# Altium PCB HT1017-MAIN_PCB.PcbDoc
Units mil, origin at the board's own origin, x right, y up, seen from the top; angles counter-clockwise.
Board outline 625 x 820 mil, 2 copper layers (Top Layer, Bottom Layer); 15 components, 37 nets, 57 pads, 70 vias.
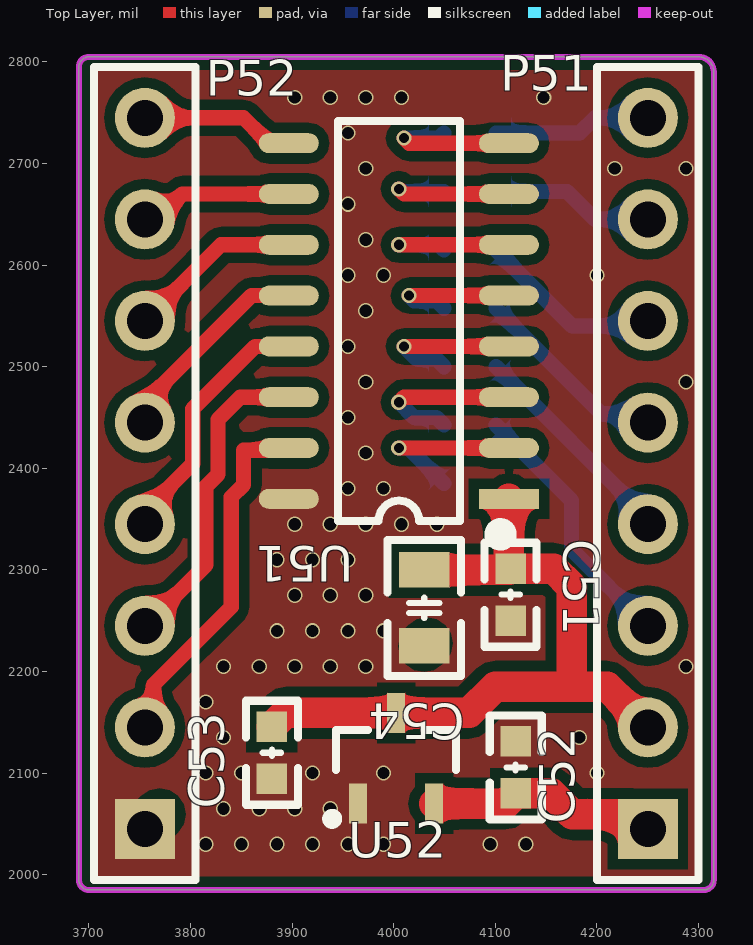
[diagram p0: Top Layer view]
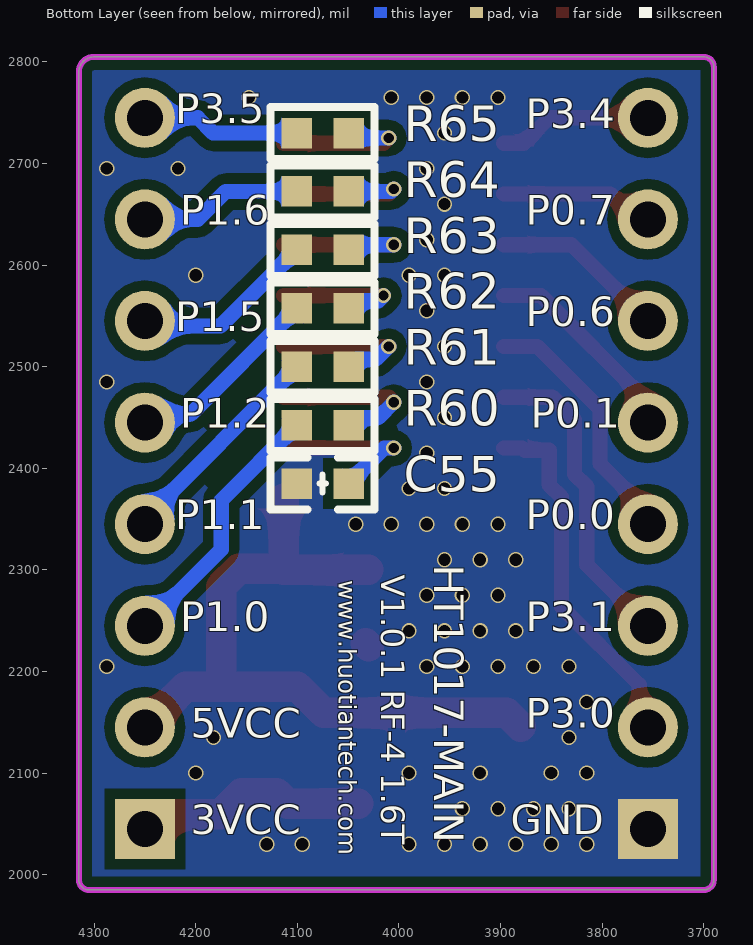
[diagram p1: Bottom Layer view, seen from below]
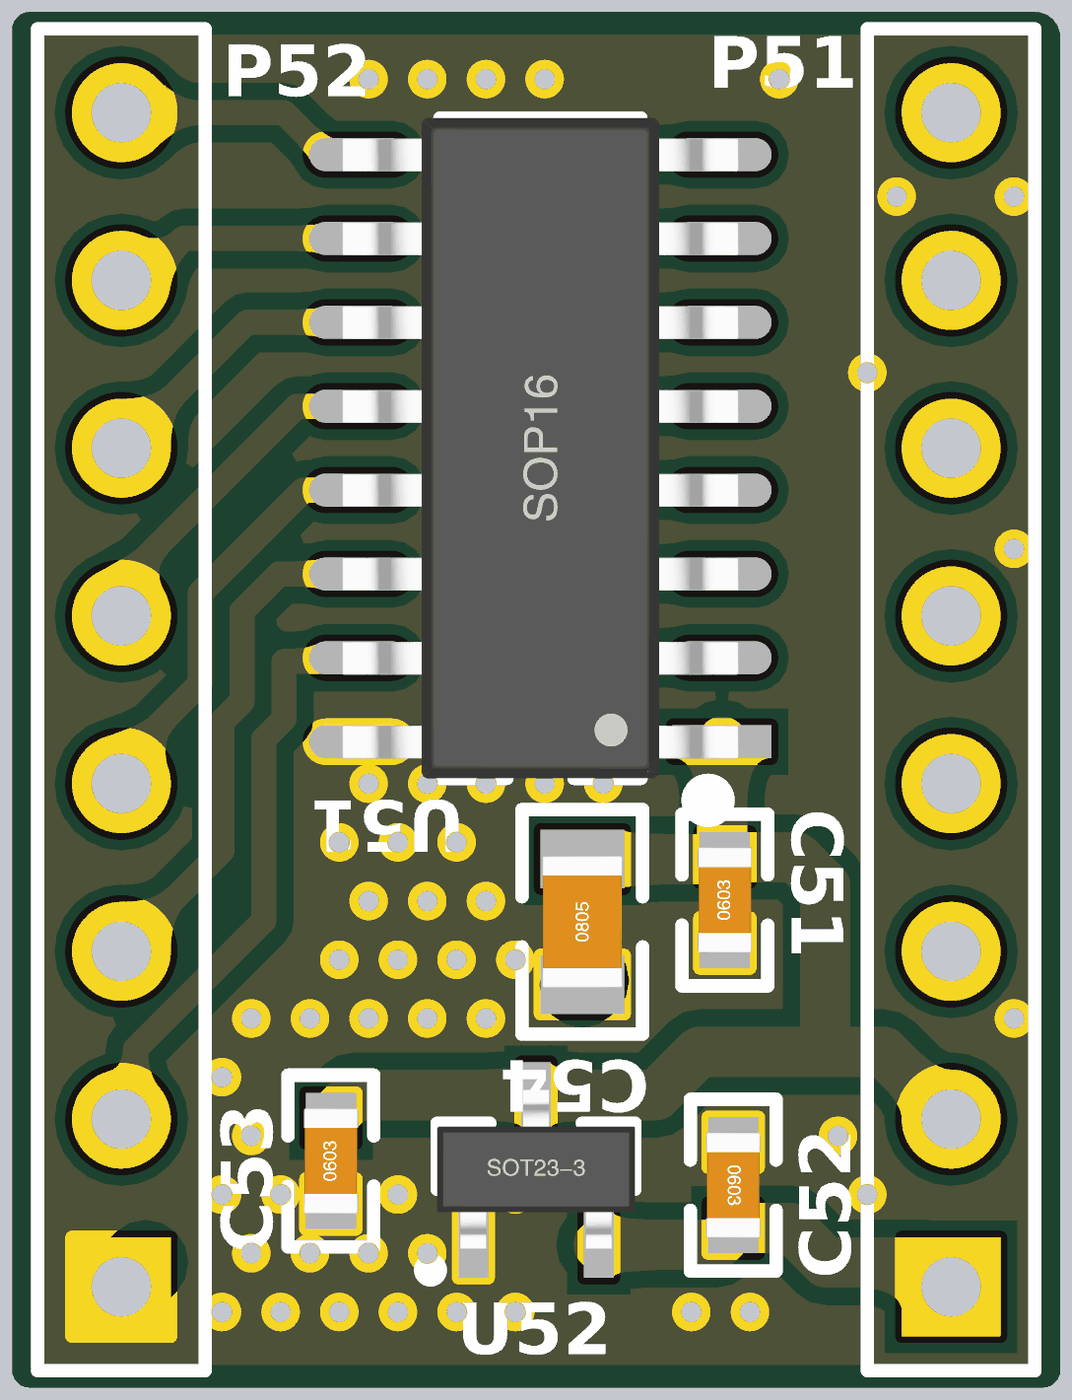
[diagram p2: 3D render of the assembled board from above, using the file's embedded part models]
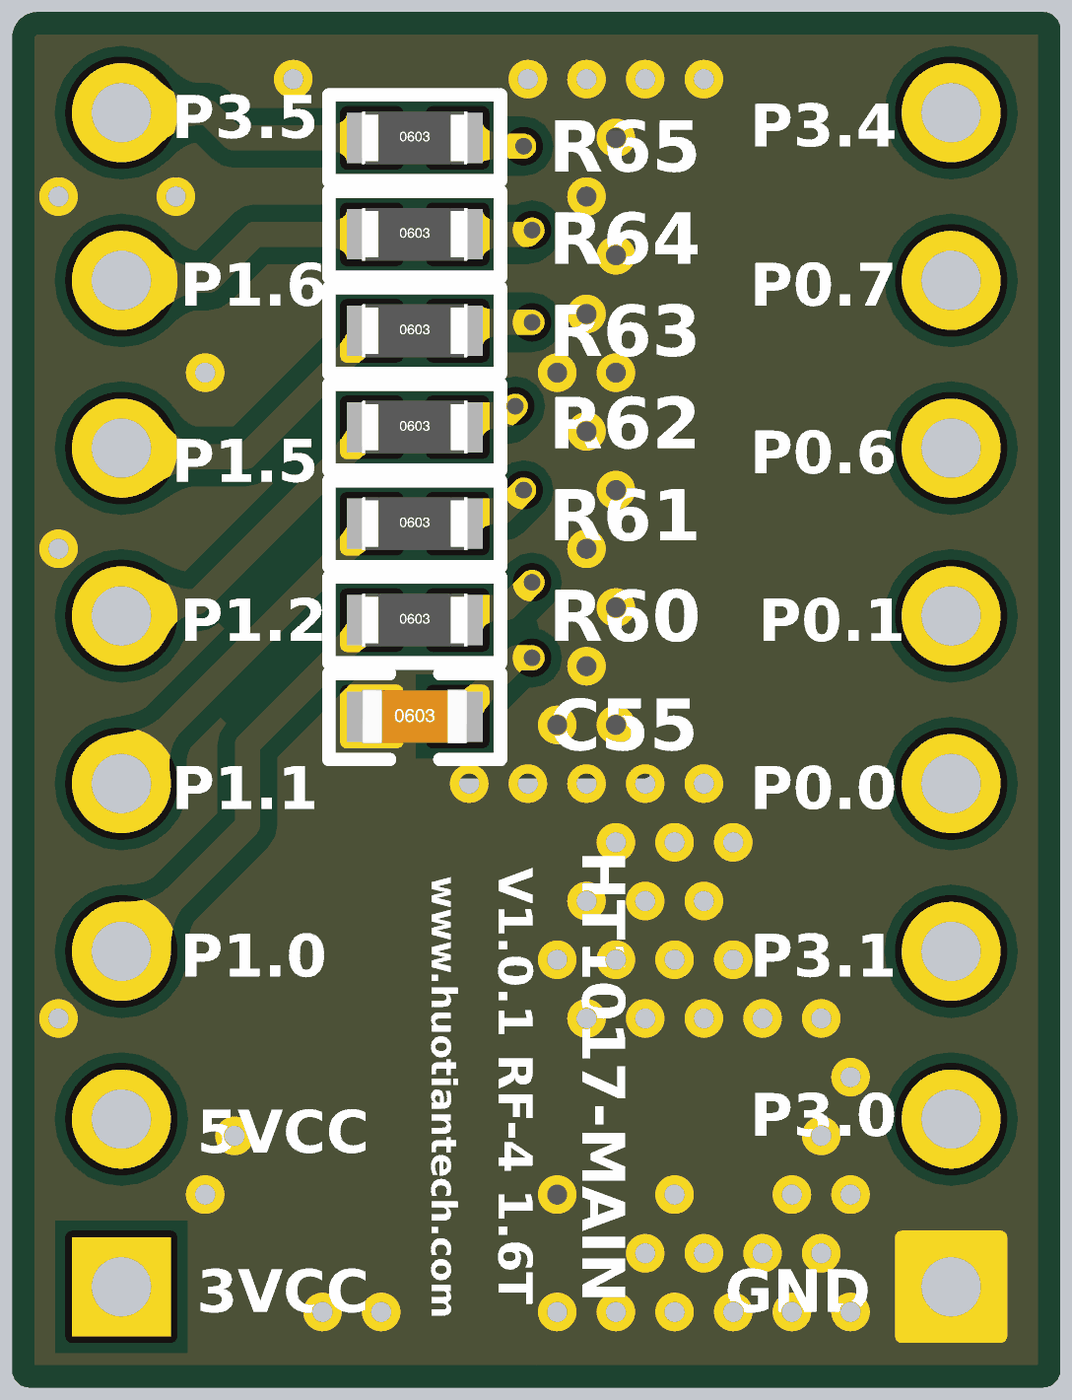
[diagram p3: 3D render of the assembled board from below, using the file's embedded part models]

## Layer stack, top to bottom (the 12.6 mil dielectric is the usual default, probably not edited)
Top Solder: solder mask 0.4, Solder Resist, Dk 3.5
Top Layer: signal copper 1.4
Dielectric 1: dielectric 12.6, FR-4, Dk 4.8
Bottom Layer: signal copper 1.4
Bottom Solder: solder mask 0.4, Solder Resist, Dk 3.5

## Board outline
3690,1995 ccw(c3700,1995) 3700,1985 4305,1985 ccw(c4305,1995) 4315,1995 4315,2790 ccw(c4300,2790) 4300,2805 3700,2805 ccw(c3700,2795) 3690,2795

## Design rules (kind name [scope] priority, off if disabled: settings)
Clearance [All] p1: gap=10 ignorepadtopadclearanceinfootprint=FALSE except(0: Arc-Hole Track-Hole SMDPad-Hole THPad-Hole Via-Hole Fill-Hole Poly-Hole Region-Hole Text-Hole)
HoleSize [All] p1: absolutevalues=TRUE maxlimit=100 minlimit=10 maxpercent=80.000 minpercent=20.000
PlaneConnect [All] p1: planeconnectstyle=Direct reliefexpansion=20 reliefentries=4 reliefconductorwidth=10 reliefairgap=10
PolygonConnect [All] p1: connectstyle=Direct reliefconductorwidth=10 reliefentries=4 polygonreliefangle="90 Angle" airgapwidth=10
RoutingVias [All] p1: holewidth=15 width=30 viastyle="Through Hole" minholewidth=10 minwidth=15 maxholewidth=30 maxwidth=50
SolderMaskExpansion [All] p1: expansion=4
Width [All] p1: maxlimit=50 minlimit=10 preferedwidth=30
28 further rules are at their usual default settings.

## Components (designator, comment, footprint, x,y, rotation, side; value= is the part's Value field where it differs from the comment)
C51 "Cap" "C 0603_L" 4115,2275.59 r90 top value=1uF
C52 "Cap" "C 0603_L" 4120,2105.59 r270 top value=1uF
C53 "Cap" "C 0603_L" 3880,2120 r90 top value=104
C54 "Cap" "C 0805_L" 4030,2262.6 r90 top value=10uF
C55 "Cap" "C 0603_L" 4075,2385 r180 bottom value=223±5%
P51 "Header 8" HDR1X8 4250,2045 r90 top
P52 "Header 8" HDR1X8 3755,2045 r90 top
R60 "Res1" "R 0603_L" 4075,2442.5 r180 bottom value=3.3K
R61 "Res1" "R 0603_L" 4075,2500 r180 bottom value=3.3K
R62 "Res1" "R 0603_L" 4075,2557.5 r180 bottom value=3.3K
R63 "Res1" "R 0603_L" 4075,2615 r180 bottom value=3.3K
R64 "Res1" "R 0603_L" 4075,2672.5 r180 bottom value=3.3K
R65 "Res1" "R 0603_L" 4075,2730 r180 bottom value=3.3K
U51 "CA51F351S3" SOP16_L 4005,2545 r180 top
U52 "XC6206P302MR" SOT23-3L 4002.4,2115 r0 top

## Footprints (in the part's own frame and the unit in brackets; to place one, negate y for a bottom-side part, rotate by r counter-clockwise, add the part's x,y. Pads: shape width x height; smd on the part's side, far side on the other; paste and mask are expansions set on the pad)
"C 0603_L" [mil] "无极性贴片电容"
  rect 30x30 smd: 1(-25.59,0) 2(25.59,0)
  silkscreen extent -51,-26 51,26, body extent -31,-16 31,16, height 32
"C 0805_L" [mil] "无极性贴片电容                    @sucaita.com 素材塔"
  rect 35x50 smd: 1(-37.4,0) 2(37.4,0)
  silkscreen extent -67,-36 67,36, body extent -39,-24 39,24, height 20
HDR1X8 [mm] "Connector; Header; 8 Position"
  rect 1.5x1.5 hole 0.9: 1(0,0)
  round 1.5 hole 0.9: 2(2.54,0) 3(5.08,0) 4(7.62,0) 5(10.16,0) 6(12.7,0) 7(15.24,0) 8(17.78,0)
  silkscreen extent -1.27,-1.27 19.05,1.27
"R 0603_L" [mil] "1/10W贴片电阻"
  rect 30x30 smd: 1(-25.59,0) 2(25.59,0)
  silkscreen extent -51,-26 51,26, body extent -31,-16 31,16, height 16
SOP16_L [mm] "10.3*6.2*1.8mm（长宽高）"
  rect 1.5x0.5 smd: 1(-2.752,4.445)
  oval 1.5x0.5 smd: 2(-2.752,3.175) 3(-2.752,1.905) 4(-2.752,0.635) 5(-2.752,-0.635) 6(-2.752,-1.905) 7(-2.752,-3.175) 8(-2.752,-4.445) 9(2.752,-4.445) 10(2.752,-3.175) 11(2.752,-1.905) 12(2.752,-0.635) 13(2.752,0.635) 14(2.752,1.905) 15(2.752,3.175) 16(2.752,4.445)
  silkscreen extent -2.69,-5 1.52,5.49, body extent -3,-5 3,5, height 1.9
SOT23-3L [mm] "3x1.3x1mm(长宽高)"
  rect 0.45x1 smd: 1(-0.95,-1.143) 2(0.95,-1.143) 3(0,1.125)
  silkscreen extent -1.72,-1.65 1.5,0.7, body extent -1.5,-1.2 1.5,1.2, height 1.05

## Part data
C51 C52 C53 C54 C55: "电容"
P51 P52: "Header, 8-Pin"
R60 R61 R62 R63 R64 R65: "电阻"
U52: "稳压IC"

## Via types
v1: diameter 15, hole 12, Top Layer to Bottom Layer, 63 vias
v2: diameter 15, hole 10, Top Layer to Bottom Layer, 7 vias

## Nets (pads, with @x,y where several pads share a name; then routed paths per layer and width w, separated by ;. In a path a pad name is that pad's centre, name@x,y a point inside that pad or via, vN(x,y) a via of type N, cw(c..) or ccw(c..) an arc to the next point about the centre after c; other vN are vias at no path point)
3.0V/VCC: C52.2 P51.1 U52.2 | length 228.8
  Top Layer w30: U52.2 4110,2070 C52.2 4155,2080 4175.47,2059.53 4235.47,2059.53 P51.1
5V/0.2A: 
5V/VCC: C51.2 C53.2 C54.2 P51.2 U51.1 U52.3 | length 724.9
  Top Layer w30: C53.2 3893.71,2159.29 U52.3 4074.07,2159.29 4099.78,2185 4170,2185 ; C54.2 4113.82,2300 4113.35,2300.47 U51.1 ; C51.2 4157.43,2301.18 4175,2283.61 4175,2190 4170,2185 ; P51.2 4210,2185 4170,2185
220V-N: 
GND: C51.1 C52.1 C53.1 C54.1 C55.1 P52.1 U51.16 U52.1 | length 24.4
  Top Layer w30: P52.1 P52.1@3769.53,2059.53 ; C54.1@4029.8,2225 C54.1 C54.1@4032.5,2227.7
  other v1: 3815,2030 3850,2030 3885,2030 3920,2030 3955,2030 3990,2030 4095,2030 4130,2030 3832.5,2065 3867.5,2065 3902.5,2065 3937.5,2065 3815,2100 3850,2100 3920,2100 3990,2100 4200,2100 3832.5,2135 4182.5,2135 3815,2170 3832.5,2205 3867.5,2205 3902.5,2205 3937.5,2205 3972.5,2205 4287.5,2205 3885,2240 3920,2240 3955,2240 3990,2240 3902.5,2275 3937.5,2275 3972.5,2275 3885,2310 3920,2310 3955,2310 3902.5,2345 3937.5,2345 3972.5,2345 4007.5,2345 4042.5,2345 3955,2380 3990,2380 3972.5,2415 3955,2450 3972.5,2485 4287.5,2485 3955,2520 3972.5,2555 3955,2590 3990,2590 4200,2590 3972.5,2625 3955,2660 3972.5,2695 4217.5,2695 4287.5,2695 3955,2730 3902.5,2765 3937.5,2765 3972.5,2765 4007.5,2765 4147.5,2765
HOT: 
Net220Vac-_1: 
NetC4_1: 
NetC4_2: 
NetC6_2: 
NetC55_2: C55.2 U51.2 | length 167.3
  Top Layer w15: v2(4005,2420) U51.2
  Bottom Layer w15: v2(4005,2420) 4014.41,2420 C55.2
NetD1_2: 
NetEC2_1: 
NetEC4_1: 
NetHOT1_1: 
NetQ1_3: 
NetQ2_1: 
NetQ2_3: 
NetR60_2: R60.2 U51.3 | length 164.2
  Top Layer w15: v2(4005,2465) 4010,2470 U51.3
  Bottom Layer w15: v2(4005,2465) 4020,2450 4041.91,2450 R60.2
NetR61_2: R61.2 U51.4 | length 151
  Top Layer w15: v2(4010,2520) U51.4
  Bottom Layer w15: v2(4010,2520) 4022.5,2507.5 4041.91,2507.5 R61.2
NetR62_2: R62.2 U51.5 | length 137.9
  Top Layer w15: v2(4015,2570) U51.5
  Bottom Layer w15: v2(4015,2570) 4020,2565 4041.91,2565 R62.2
NetR63_2: R63.2 U51.6 | length 154.8
  Top Layer w15: v2(4005,2620) U51.6
  Bottom Layer w15: v2(4005,2620) 4044.41,2620 R63.2
NetR64_2: R64.2 U51.7 | length 155.9
  Top Layer w15: v2(4005,2675) 4010,2670 U51.7
  Bottom Layer w15: v2(4005,2675) 4007.5,2672.5 R64.2
NetR65_2: R65.2 U51.8 | length 146.9
  Top Layer w15: v2(4010,2725) 4015,2720 U51.8
  Bottom Layer w15: v2(4010,2725) 4044.41,2725 R65.2
P0.0: P52.4 U51.13 | length 263
  Top Layer w15: P52.4@3765,2345 P52.4 3755,2357.41 3802.03,2404.44 3802.03,2458.44 3863.59,2520 U51.13
P0.1: P52.5 U51.12 | length 205.1
  Top Layer w15: P52.5 3755,2465 3860,2570 U51.12
P0.6: P52.6 U51.11 | length 172.7
  Top Layer w15: P52.6 3830,2620 U51.11
P0.7: P52.7 U51.10 | length 152
  Top Layer w15: P52.7 3766.92,2645 3791.92,2670 U51.10
P1.0: P51.3 R60.1 | length 259.4
  Bottom Layer w15: R60.1 4174.83,2368.26 4174.83,2320.17 P51.3
P1.1: P51.4 R61.1 | length 216.9
  Bottom Layer w15: R61.1 4250,2350.59 P51.4
P1.2: P51.5 R62.1 | length 196
  Bottom Layer w15: R62.1 4204.66,2453.43 4241.57,2453.43 P51.5
P1.5: P51.6 R63.1 | length 182.5
  Bottom Layer w15: R63.1 4175.59,2540 4245,2540 P51.6
P1.6: P51.7 R64.1 | length 160.8
  Bottom Layer w15: R64.1 4170.47,2672.5 4197.97,2645 P51.7
P3.0: P52.2 U51.15 | length 358.5
  Top Layer w15: P52.2 3763.43,2153.43 3763.43,2186.92 3840,2263.49 3840,2371.7 3852.03,2383.73 3852.03,2417.84 3876.07,2417.84 3878.24,2420 U51.15
P3.1: P52.3 U51.14 | length 311.6
  Top Layer w15: P52.3 3815,2305 3815,2382.05 3827.03,2394.08 3827.03,2448.08 3848.95,2470 U51.14
P3.4: P52.8 U51.9 | length 152
  Top Layer w15: P52.8 3851.97,2745 3876.97,2720 U51.9
P3.5: P51.8 R65.1 | length 155.6
  Bottom Layer w15: R65.1 4182.97,2730 4197.97,2745 P51.8

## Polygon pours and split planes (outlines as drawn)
GND on Bottom Layer (solid, remove dead copper, pour order 16): 3635,2880 4370,2880 4370,1815 4285,1730 3500,1730
GND on Top Layer (solid, remove dead copper, pour order 14): 3635,2870 4300,2870 4390,2780 4390,1900 3660,1900 3650,1910

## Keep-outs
Keep-Out Layer:
  the board outline again, w6

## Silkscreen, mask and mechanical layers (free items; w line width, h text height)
Bottom Overlay:
  text "P3.5" at 4220,2730 h50
  text "P3.4" at 3875,2725 h50
  text "P0.7" at 3875,2630 h50
  text "P1.6" at 4215,2630 h50
  text "P0.6" at 3875,2530 h50
  text "P1.5" at 4220,2525 h50
  text "P0.1" at 3870,2430 h50
  text "P1.2" at 4215,2430 h50
  text "P0.0" at 3875,2330 h50
  text "P1.1" at 4220,2330 h50
  text "HT1017-MAIN" at 3975,2305 h50 r90
  text "V1.0.1 RF-4 1.6T" at 4025,2295 h40 r90
  text "www.huotiantech.com" at 4065,2290 h30 r90
  text "P3.1" at 3875,2230 h50
  text "P1.0" at 4215,2230 h50
  text "P3.0" at 3875,2135 h50
  text "5VCC" at 4205,2125 h50
  text "GND" at 3890,2030 h50
  text "3VCC" at 4205,2030 h50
